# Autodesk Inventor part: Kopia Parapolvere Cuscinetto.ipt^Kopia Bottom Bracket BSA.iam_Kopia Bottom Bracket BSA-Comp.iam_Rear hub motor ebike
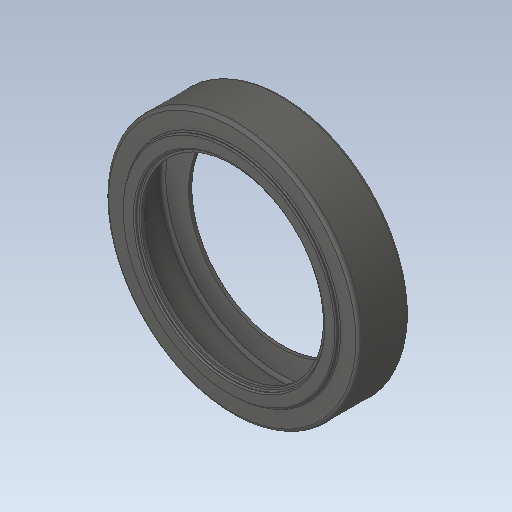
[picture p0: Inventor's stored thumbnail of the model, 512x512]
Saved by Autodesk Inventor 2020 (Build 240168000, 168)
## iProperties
Created: 2017-11
Part Number: Kopia Parapolvere Cuscinetto.ipt^Kopia Bottom Bracket BSA.iam_Kopia Bottom Bracket BSA-Comp.iam_Rear hub motor ebike
Material: Ogólny
Document SubType Name: Modeling
Designer: Tomasz
Density: 1 g/cm^3
Appearance: Domyślna
Sending System: SolidWorks 2017
Last Author: Tomasz
Last Saved: 2017-11-19
Author: Tomasz
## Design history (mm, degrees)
feature "Parapolvere Cuscinetto.ipt"
node "Bryła1"
